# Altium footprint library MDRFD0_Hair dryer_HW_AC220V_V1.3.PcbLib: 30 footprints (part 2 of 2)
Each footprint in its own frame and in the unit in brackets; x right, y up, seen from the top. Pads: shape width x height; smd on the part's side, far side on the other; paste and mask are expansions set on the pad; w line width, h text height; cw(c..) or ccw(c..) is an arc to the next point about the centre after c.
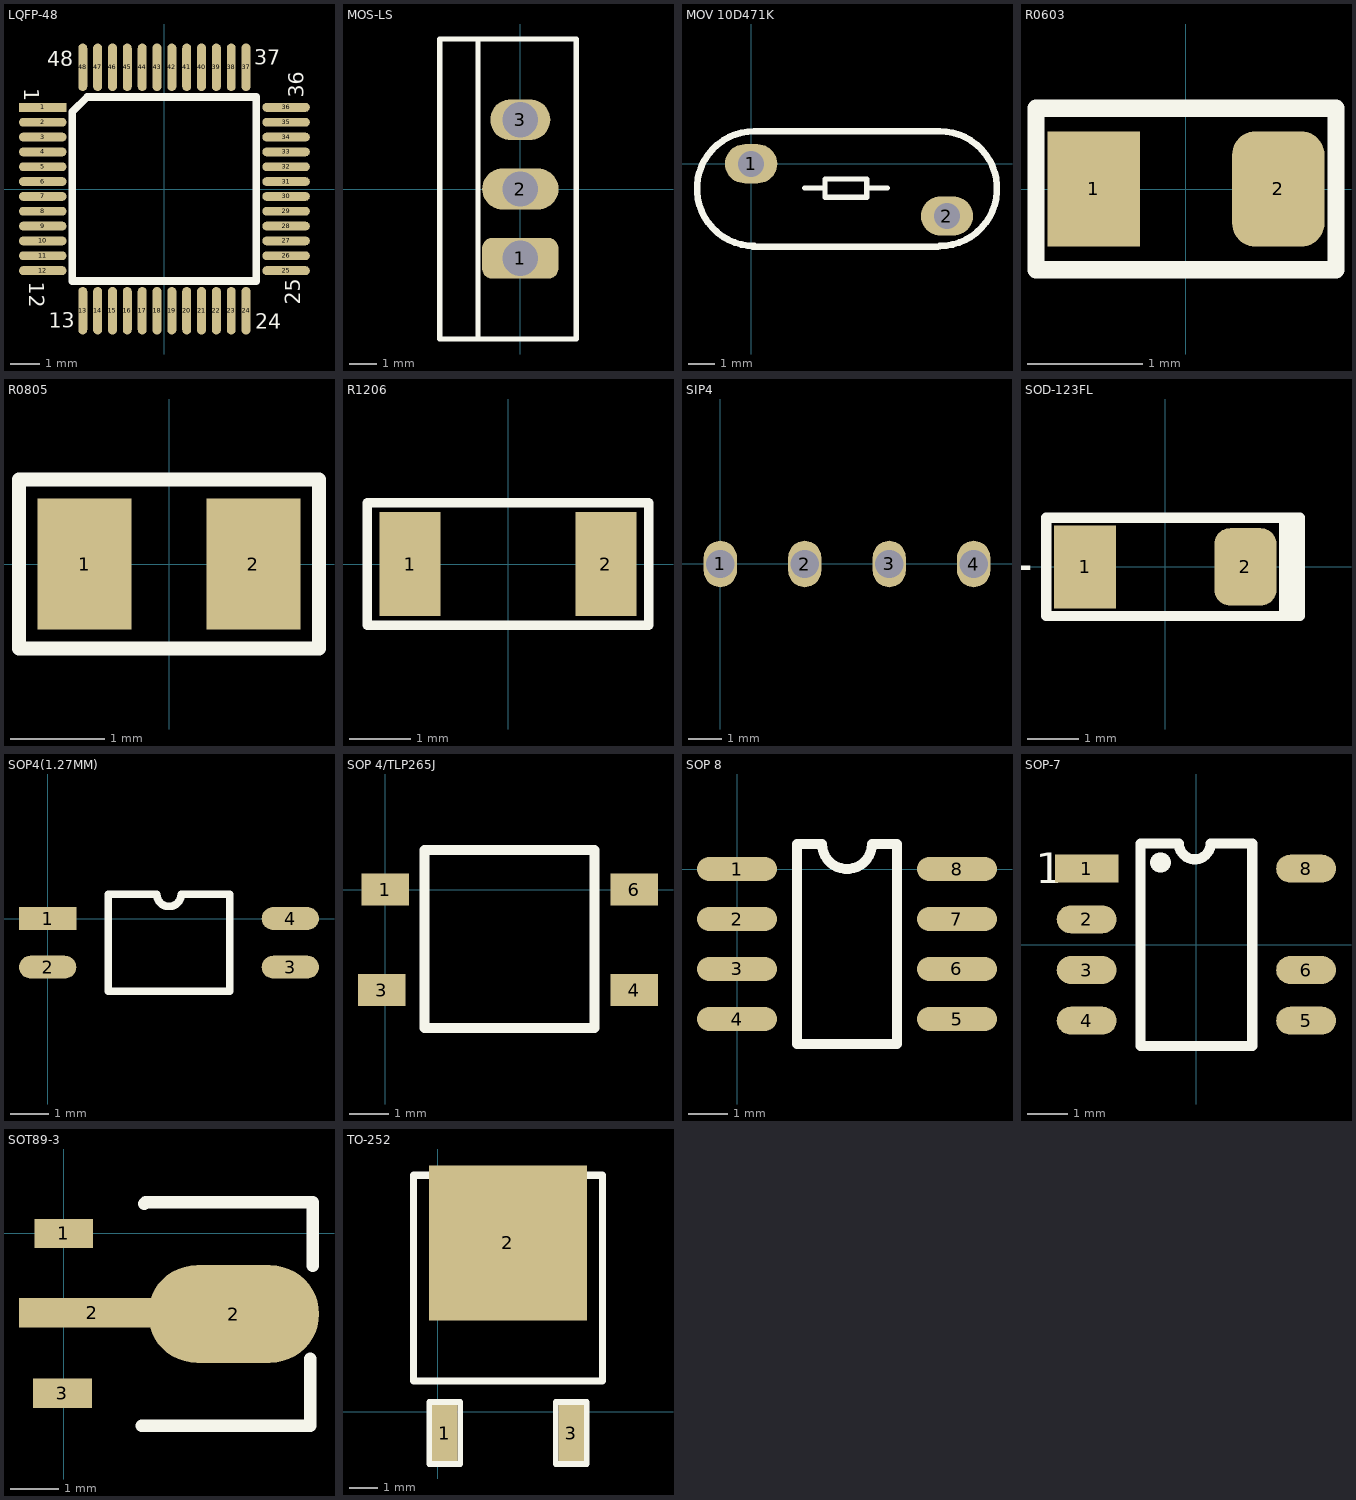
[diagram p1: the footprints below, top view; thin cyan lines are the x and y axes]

## LQFP-48 [mm]
pads (49):
  rect 1.6x0.3 smd: 1(-4.1,2.75)
  oval 1.6x0.3 smd: 2(-4.1,2.25) 3(-4.1,1.75) 4(-4.1,1.25) 5(-4.1,0.75) 6(-4.1,0.25) 7(-4.1,-0.25) 8(-4.1,-0.75) 9(-4.1,-1.25) 10(-4.1,-1.75) 11(-4.1,-2.25) 12(-4.1,-2.75) 25(4.1,-2.75) 26(4.1,-2.25) 27(4.1,-1.75) 28(4.1,-1.25) 29(4.1,-0.75) 30(4.1,-0.25) 31(4.1,0.25) 32(4.1,0.75) 33(4.1,1.25) 34(4.1,1.75) 35(4.1,2.25) 36(4.1,2.75)
  oval 0.3x1.6 smd: 13(-2.75,-4.1) 14(-2.25,-4.1) 15(-1.75,-4.1) 16(-1.25,-4.1) 17(-0.75,-4.1) 18(-0.25,-4.1) 19(0.25,-4.1) 20(0.75,-4.1) 21(1.25,-4.1) 22(1.75,-4.1) 23(2.25,-4.1) 24(2.75,-4.1) 37(2.75,4.1) 38(2.25,4.1) 39(1.75,4.1) 40(1.25,4.1) 41(0.75,4.1) 42(0.25,4.1) 43(-0.25,4.1) 44(-0.75,4.1) 45(-1.25,4.1) 46(-1.75,4.1) 47(-2.25,4.1) 48(-2.75,4.1)
  round 0.5 on Top Overlay: ""(-2.4,2.4)
Top Overlay:
  lines w0.254: -3.1,-3.1 -3.1,2.6 -2.6,3.1 3.1,3.1 3.1,-3.1 -3.1,-3.1
  text "1" at -4.73,3.4 h0.51
  text "12" at -4.56,-3.12 h0.51
  text "13" at -3.9,-4.67 h0.51
  text "24" at 3.06,-4.71 h0.51
  text "25" at 4.58,-3.9 h0.51
  text "36" at 4.7,3.08 h0.51
  text "37" at 3.03,4.18 h0.51
  text "48" at -3.94,4.14 h0.51
3D body: height 1.45, standoff 0, extent -4.5,-4.5 4.5,4.5

## MOS-LS [mm]
pads (3):
  rrect50% 2.8x1.5 hole 1.3: 1(0,-2.54)
  oval 2.8x1.5 hole 1.3: 2(0,0)
  oval 2.2x1.5 hole 1.3: 3(0,2.54)
Top Overlay:
  lines w0.2: -1.55,-5.5 -1.55,5.5 ; -2.95,-5.5 -2.95,5.5 2.05,5.5 2.05,-5.5 -2.95,-5.5

## MOV 10D471K [mm] "VDR,¶¡¶Z7.5mmª½®"
pads (2):
  oval 2x1.5 hole 1: 1(0,0) 2(7.5,-2)
Top Overlay:
  lines w0.2: 2.053,-0.93 2.815,-0.93 ; 4.428,-0.93 5.228,-0.93 ; 2.828,-1.28 2.828,-0.58 4.428,-0.58 4.428,-1.28 2.828,-1.28
  lines w0.25: 0.06,-3.18 4.26,-3.18 ; 0.125,1.25 4.325,1.25
  lines w0.254: 0.125,-3.15 cw(c0.125,-0.95) 0.125,1.25 ; 4.26,-3.18 7.155,-3.18 ; 4.325,1.25 7.22,1.25 cw(c7.22,-0.95) 7.22,-3.15

## R0603 [mm]
pads (2):
  rect 0.8x1 smd: 1(-0.8,0)
  rrect50% 0.8x1 smd: 2(0.8,0)
Top Overlay:
  lines w0.15: -1.3,-0.7 1.3,-0.7 1.3,0.7 -1.3,0.7 -1.3,-0.7
3D body: height 0.5, standoff 0, extent -0.8,-0.45 0.8,0.45

## R0805 [mm]
pads (2):
  rect 1x1.4 smd: 1(-0.9,0) 2(0.9,0)
Top Overlay:
  lines w0.15: -1.6,-0.9 1.6,-0.9 1.6,0.9 -1.6,0.9 -1.6,-0.9
3D body: height 0.45, standoff 0, extent -1,-0.625 1,0.625

## R1206 [mm]
pads (2):
  rect 1x1.7 smd: 1(-1.6,0) 2(1.6,0)
Top Overlay:
  lines w0.15: -2.3,-1 -2.3,1 2.3,1 2.3,-1 -2.3,-1
3D body: height 0.55, standoff 0, extent -1.6,-0.8 1.6,0.8

## SIP4 [mm]
pads (4):
  oval 1x1.4 hole 0.85: 1(0,0) 2(2.54,0) 3(5.08,0) 4(7.62,0)

## SOD-123FL [mm]
pads (2):
  rect 1.2x1.6 smd: 1(-1.55,0)
  rrect50% 1.2x1.5 smd: 2(1.55,0)
Top Overlay:
  region: 2.525,-0.98 2.525,0.9 2.2,0.9 2.2,-0.98
  lines w0.2: -2.3,-0.95 2.6,-0.95 2.6,0.95 -2.3,0.95 -2.3,-0.95
  text "+" at -2.5,0.3 h0.76
3D body: height 1.25, standoff 0, extent -1.849,-0.8 1.849,0.8

## SOP4(1.27MM) [mm]
pads (4):
  rect 1.5x0.6 smd: 1(0,0)
  oval 1.5x0.6 smd: 2(0,-1.27) 3(6.35,-1.27) 4(6.35,0)
Top Overlay:
  lines w0.2: 1.585,-1.905 4.765,-1.905 4.765,0.635 3.492,0.635 cw(c3.175,0.635) 2.857,0.635 1.585,0.635 1.585,-1.905

## SOP 4/TLP265J [mm]
pads (4):
  rect 1.2x0.8 smd: 1(0,0) 3(-0.085,-2.54) 4(6.3,-2.54) 6(6.3,0)
Top Overlay:
  lines w0.254: 1,-3.5 1,1 5.3,1 5.3,-3.5 1,-3.5
  text "." at 1.555,0.025 h1.52

## SOP 8 [mil]
pads (8):
  oval 80x24 smd: 1(0,0) 2(0,-50) 3(0,-100) 4(0,-150) 5(220,-150) 6(220,-100) 7(220,-50) 8(220,0)
Top Overlay:
  lines w10: 60,-175 60,25 85,25 ccw(c110,25) 135,25 160,25 160,-175 60,-175
3D body: height 62.99, standoff 0, extent -8.93,-173.81 228.94,23.82

## SOP-7 [mm]
height 22
pads (7):
  rect 1.6x0.7 smd: 1(-2.75,1.905)
  oval 1.5x0.7 smd: 2(-2.75,0.635) 3(-2.75,-0.635) 4(-2.75,-1.905) 5(2.75,-1.905) 6(2.75,-0.635) 8(2.75,1.905)
Top Overlay:
  lines w0.254: -1.4,-2.54 1.4,-2.54 1.4,2.54 0.361,2.54 cw(c-0.039,2.54) -0.439,2.54 -1.4,2.54 -1.4,-2.54
  lines w0.5: -0.91,2.055 -0.885,2.055
  text "1" at -4.02,1.545 h0.76
3D body: height 1.6, standoff 0, extent -3.051,-2.49 2.991,2.53

## SOT89-3 [mm]
pads (4):
  rect 1.2x0.6 smd: 1(0,0) 3(-0.025,-3.277)
  rect 3x0.6 smd: 2(0.584,-1.626)
  oval 3.5x2 smd: 2(3.48,-1.651)
Top Overlay:
  lines w0.254: 1.6,-3.937 5.055,-3.937 5.055,-2.819 5.055,-2.565 ; 1.651,0.61 1.676,0.635 5.105,0.635 5.105,-0.66
3D body: height 1.4, standoff 0, extent 0.318,-3.865 4.253,0.635

## TO-252 [mm]
pads (3):
  rect 0.9x2 smd: 1(0.25,-0.75) 3(4.75,-0.75)
  rect 5.6x5.5 smd: 2(2.5,6)
Top Overlay:
  lines w0.2: -0.85,1.1 5.85,1.1 ; -0.3,-1.85 0.8,-1.85 0.8,0.35 -0.3,0.35 -0.3,-1.85 ; 4.2,-1.85 5.3,-1.85 5.3,0.35 4.2,0.35 4.2,-1.85
  lines w0.254: -0.85,1.1 -0.85,8.4 5.85,8.4 5.85,1.1 -0.85,1.1
3D body: height 2.37, standoff -0.03, extent -0.827,-1.526 5.907,8.574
